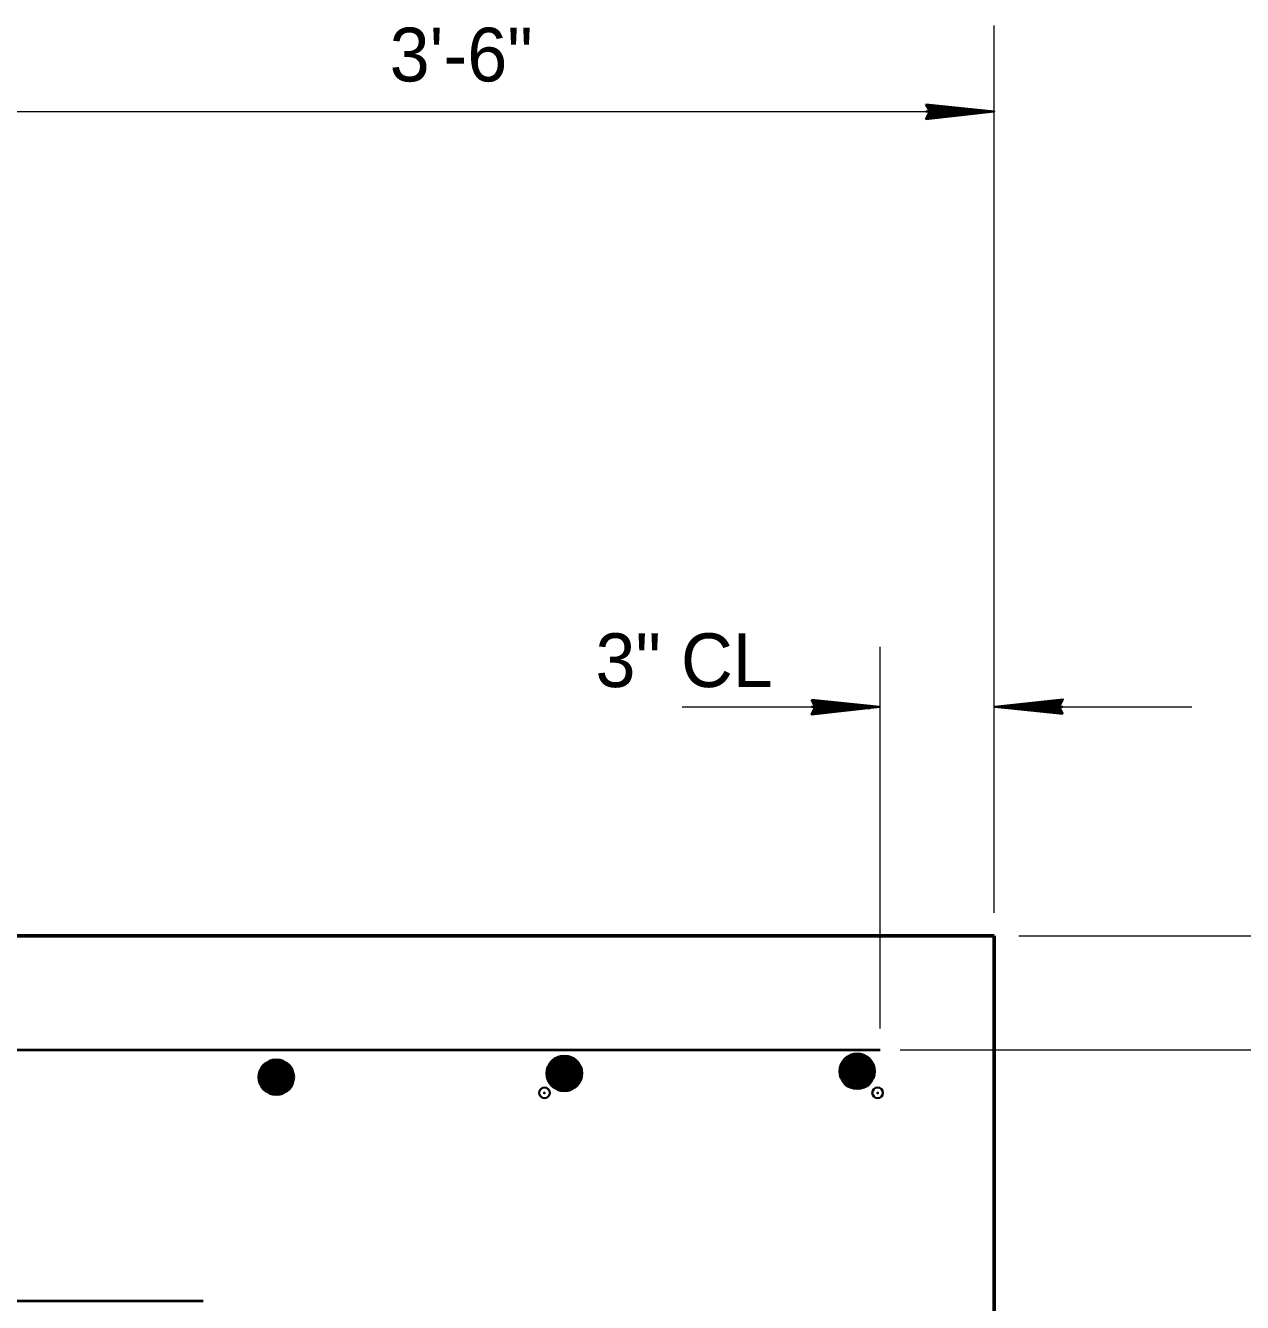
# Model space of a CAD drawing. Extents: x 4.49 to 7.69, y 0.28 to 2.27.
# Drawn here: x 6.6993 to 6.888, y 1.8987 to 2.0968 of the extents above; entities that cross this region are included whole.
import ezdxf

# ---------------------------------------------------------------- set-up
doc = ezdxf.new("R2010")
doc.units = 0
doc.header["$LTSCALE"] = 0.0033
doc.header["$PDMODE"] = 32
doc.header["$PDSIZE"] = 0.00165
doc.layers.add('1', color=7, linetype='Continuous', lineweight=35)

msp = doc.modelspace()

# ---------------------------------------------------------------- linework, layer by layer
at = {"layer": '1', "lineweight": 13}
for p, q in [((6.8495, 1.959167), (6.8495, 2.09675)), ((6.35025, 2.083417), (6.848917, 2.083417)), ((6.831833, 1.94125), (6.831833, 2.000417)), ((6.801083, 1.991083), (6.821917, 1.991083)), ((6.859333, 1.991083), (6.880167, 1.991083)), ((6.853333, 1.955583), (6.932833, 1.955583)), ((6.834917, 1.937917), (6.90475, 1.937917))]:
    msp.add_line(p, q, dxfattribs=at)
at = {"layer": '1'}
for p, q in [((6.838917, 2.083417), (6.8495, 2.083417)), ((6.839083, 2.08275), (6.846417, 2.0835)), ((6.839167, 2.084417), (6.847, 2.0835)), ((6.839167, 2.084417), (6.847, 2.0835)), ((6.839167, 2.084333), (6.847, 2.0835)), ((6.839167, 2.08425), (6.847, 2.083417)), ((6.839167, 2.08425), (6.847, 2.08325)), ((6.839167, 2.082583), (6.8465, 2.083417)), ((6.839167, 2.0825), (6.8465, 2.08325)), ((6.839167, 2.082333), (6.8465, 2.083167)), ((6.821417, 1.992083), (6.82925, 1.991167)), ((6.821417, 1.992083), (6.82925, 1.991167)), ((6.821417, 1.992), (6.82925, 1.991167)), ((6.859917, 1.992167), (6.852583, 1.991333)), ((6.859917, 1.992), (6.852583, 1.99125)), ((6.821167, 1.991083), (6.83175, 1.991083)), ((6.821333, 1.990417), (6.828667, 1.991167)), ((6.821417, 1.991917), (6.82925, 1.991083)), ((6.821417, 1.991917), (6.82925, 1.990917)), ((6.821417, 1.99025), (6.82875, 1.991083)), ((6.821417, 1.990167), (6.82875, 1.990917)), ((6.821417, 1.99), (6.82875, 1.990833)), ((6.860167, 1.991083), (6.849583, 1.991083)), ((6.859917, 1.99025), (6.852083, 1.99125)), ((6.859917, 1.99025), (6.852083, 1.991083)), ((6.859917, 1.990083), (6.852083, 1.991)), ((6.859917, 1.990083), (6.852083, 1.991)), ((6.859917, 1.990167), (6.852083, 1.991)), ((6.859917, 1.991917), (6.852583, 1.991083)), ((6.86, 1.99175), (6.852667, 1.991))]:
    msp.add_line(p, q, dxfattribs=at)
at = {"layer": '1', "lineweight": 40}
for p, q in [((6.367167, 1.937917), (6.831833, 1.937917)), ((6.785167, 1.9355), (6.783917, 1.936667)), ((6.826583, 1.9365), (6.830417, 1.935833)), ((6.8285, 1.935667), (6.829833, 1.936667)), ((6.830583, 1.935833), (6.829333, 1.937)), ((6.736083, 1.93525), (6.740667, 1.933083)), ((6.736333, 1.934833), (6.74025, 1.934083)), ((6.736333, 1.934667), (6.74025, 1.933917)), ((6.736417, 1.93525), (6.740333, 1.934583)), ((6.736417, 1.935083), (6.740333, 1.934333)), ((6.7365, 1.935583), (6.740333, 1.934917)), ((6.738417, 1.93475), (6.73975, 1.93575)), ((6.7405, 1.934917), (6.73925, 1.936083)), ((6.78075, 1.935833), (6.785333, 1.933667)), ((6.780917, 1.934833), (6.78475, 1.934167)), ((6.780917, 1.934667), (6.78475, 1.933917)), ((6.781, 1.935417), (6.784917, 1.934667)), ((6.781, 1.93525), (6.784917, 1.9345)), ((6.781, 1.935), (6.784833, 1.93425)), ((6.781083, 1.935833), (6.785, 1.935167)), ((6.781083, 1.935667), (6.785, 1.934917)), ((6.781167, 1.936167), (6.785, 1.9355)), ((6.783083, 1.935333), (6.784417, 1.936333)), ((6.826167, 1.936167), (6.83075, 1.934)), ((6.82625, 1.93475), (6.830083, 1.934)), ((6.82625, 1.934583), (6.830083, 1.933833)), ((6.826333, 1.935167), (6.830167, 1.9345)), ((6.826333, 1.935), (6.830167, 1.93425)), ((6.826417, 1.93575), (6.830333, 1.935)), ((6.826417, 1.935583), (6.830333, 1.934833)), ((6.826417, 1.935333), (6.83025, 1.934583)), ((6.8265, 1.936167), (6.830417, 1.9355)), ((6.8265, 1.936), (6.830417, 1.93525)), ((6.736, 1.933), (6.739917, 1.93225)), ((6.736, 1.932833), (6.739833, 1.932083)), ((6.736, 1.932583), (6.739833, 1.931917)), ((6.736083, 1.933417), (6.74, 1.932667)), ((6.736167, 1.933833), (6.74, 1.933083)), ((6.736167, 1.933667), (6.74, 1.932917)), ((6.73625, 1.93425), (6.740083, 1.933583)), ((6.73625, 1.934083), (6.740083, 1.933333)), ((6.736333, 1.934417), (6.740167, 1.933667)), ((6.780583, 1.933083), (6.784417, 1.932333)), ((6.780583, 1.932917), (6.784417, 1.932167)), ((6.780667, 1.933583), (6.784583, 1.932833)), ((6.780667, 1.933417), (6.7845, 1.932667)), ((6.780667, 1.933167), (6.7845, 1.9325)), ((6.78075, 1.934), (6.784667, 1.93325)), ((6.780833, 1.934417), (6.784667, 1.933667)), ((6.780833, 1.93425), (6.784667, 1.9335)), ((6.784917, 1.932667), (6.781167, 1.93225)), ((6.826, 1.933417), (6.829833, 1.932667)), ((6.826, 1.93325), (6.829833, 1.9325)), ((6.826083, 1.933917), (6.83, 1.933167)), ((6.826083, 1.93375), (6.829917, 1.933)), ((6.826083, 1.9335), (6.829917, 1.932833)), ((6.826167, 1.934333), (6.830083, 1.933583)), ((6.830333, 1.933), (6.826583, 1.932583)), ((6.735917, 1.9325), (6.73975, 1.93175)), ((6.735917, 1.932333), (6.73975, 1.931583)), ((6.74025, 1.932083), (6.7365, 1.931667))]:
    msp.add_line(p, q, dxfattribs=at)
at = {"layer": '1', "lineweight": 60}
for p, q in [((6.736333, 1.93525), (6.736167, 1.932333)), ((6.736583, 1.93525), (6.736333, 1.932333)), ((6.73675, 1.93525), (6.736583, 1.93225)), ((6.736917, 1.93525), (6.736667, 1.93225)), ((6.737083, 1.93525), (6.736917, 1.93225)), ((6.737333, 1.93525), (6.737167, 1.93225)), ((6.737583, 1.93525), (6.737333, 1.93225)), ((6.737667, 1.935167), (6.7375, 1.93225)), ((6.737833, 1.935167), (6.737667, 1.93225)), ((6.738, 1.935167), (6.737833, 1.93225)), ((6.73825, 1.935167), (6.738, 1.93225)), ((6.738417, 1.935167), (6.73825, 1.93225)), ((6.738667, 1.935083), (6.738417, 1.932167)), ((6.738917, 1.935083), (6.738667, 1.932167)), ((6.739083, 1.935083), (6.738917, 1.932167)), ((6.739167, 1.935083), (6.739, 1.932167)), ((6.739333, 1.935083), (6.739167, 1.932167)), ((6.739417, 1.935083), (6.73925, 1.932167)), ((6.739667, 1.935), (6.739417, 1.932083)), ((6.739833, 1.935), (6.739667, 1.932083)), ((6.74, 1.935), (6.73975, 1.932083)), ((6.740167, 1.935), (6.74, 1.932083)), ((6.740417, 1.935), (6.74025, 1.932083)), ((6.740667, 1.933083), (6.7405, 1.934917)), ((6.781, 1.935833), (6.780833, 1.932917)), ((6.78125, 1.935833), (6.781, 1.932917)), ((6.781417, 1.935833), (6.78125, 1.932833)), ((6.781583, 1.935833), (6.781333, 1.932833)), ((6.78175, 1.935833), (6.781583, 1.932833)), ((6.782, 1.935833), (6.781833, 1.932833)), ((6.78225, 1.935833), (6.782, 1.932833)), ((6.782333, 1.93575), (6.782167, 1.932833)), ((6.7825, 1.93575), (6.782333, 1.932833)), ((6.782667, 1.93575), (6.7825, 1.932833)), ((6.782917, 1.93575), (6.782667, 1.932833)), ((6.783083, 1.93575), (6.782917, 1.932833)), ((6.783333, 1.935667), (6.783083, 1.93275)), ((6.783583, 1.935667), (6.783333, 1.93275)), ((6.78375, 1.935667), (6.783583, 1.93275)), ((6.783833, 1.935667), (6.783667, 1.93275)), ((6.784, 1.935667), (6.783833, 1.93275)), ((6.784083, 1.935667), (6.783917, 1.93275)), ((6.784333, 1.935583), (6.784083, 1.932667)), ((6.7845, 1.935583), (6.784333, 1.932667)), ((6.784667, 1.935583), (6.784417, 1.932667)), ((6.784833, 1.935583), (6.784667, 1.932667)), ((6.785083, 1.935583), (6.784917, 1.932667)), ((6.785333, 1.933667), (6.785167, 1.9355)), ((6.826417, 1.936167), (6.82625, 1.93325)), ((6.826667, 1.936167), (6.826417, 1.93325)), ((6.826833, 1.936167), (6.826667, 1.933167)), ((6.827, 1.936167), (6.82675, 1.933167)), ((6.827167, 1.936167), (6.827, 1.933167)), ((6.827417, 1.936167), (6.82725, 1.933167)), ((6.827667, 1.936167), (6.827417, 1.933167)), ((6.82775, 1.936083), (6.827583, 1.933167)), ((6.827917, 1.936083), (6.82775, 1.933167)), ((6.828083, 1.936083), (6.827917, 1.933167)), ((6.828333, 1.936083), (6.828083, 1.933167)), ((6.8285, 1.936083), (6.828333, 1.933167)), ((6.82875, 1.936), (6.8285, 1.933083)), ((6.829, 1.936), (6.82875, 1.933083)), ((6.829167, 1.936), (6.829, 1.933083)), ((6.82925, 1.936), (6.829083, 1.933083)), ((6.829417, 1.936), (6.82925, 1.933083)), ((6.8295, 1.936), (6.829333, 1.933083)), ((6.82975, 1.935917), (6.8295, 1.933)), ((6.829917, 1.935917), (6.82975, 1.933)), ((6.830083, 1.935917), (6.829833, 1.933)), ((6.83025, 1.935917), (6.830083, 1.933)), ((6.8305, 1.935917), (6.830333, 1.933)), ((6.83075, 1.934), (6.830583, 1.935833)), ((6.740667, 1.933083), (6.735917, 1.932333)), ((6.785333, 1.933667), (6.780583, 1.932917)), ((6.83075, 1.934), (6.826, 1.93325))]:
    msp.add_line(p, q, dxfattribs=at)
at = {"layer": '1'}
for points in [[(6.838917, 2.0845), (6.8495, 2.083417), (6.838917, 2.08225), (6.8395, 2.083417)], [(6.839667, 2.0835), (6.844333, 2.083583), (6.844333, 2.0835), (6.843417, 2.0835), (6.839667, 2.083583), (6.842667, 2.083667), (6.8395, 2.08375), (6.84175, 2.083833), (6.8395, 2.083917), (6.843, 2.083667), (6.847667, 2.0835), (6.84675, 2.08325), (6.848, 2.08325), (6.839667, 2.08325), (6.842083, 2.083083), (6.8395, 2.083083), (6.844833, 2.0835), (6.8395, 2.082833)], [(6.821167, 1.992167), (6.83175, 1.991083), (6.821167, 1.989917), (6.82175, 1.991083)], [(6.860167, 1.99), (6.849583, 1.991083), (6.860167, 1.99225), (6.859583, 1.991083)], [(6.821917, 1.991167), (6.826583, 1.99125), (6.826583, 1.991167), (6.825667, 1.991167), (6.821917, 1.99125), (6.824917, 1.991333), (6.82175, 1.991417), (6.824, 1.9915), (6.82175, 1.991583), (6.82525, 1.991333), (6.829917, 1.991167), (6.829, 1.990917), (6.83025, 1.990917), (6.821917, 1.990917), (6.824333, 1.99075), (6.82175, 1.99075), (6.827083, 1.991167), (6.82175, 1.9905)], [(6.859417, 1.991), (6.85475, 1.990917), (6.85475, 1.991), (6.855667, 1.991), (6.859417, 1.990917), (6.856417, 1.990833), (6.859583, 1.99075), (6.857333, 1.990667), (6.859583, 1.990583), (6.856083, 1.990833), (6.851417, 1.991), (6.852333, 1.99125), (6.851083, 1.99125), (6.859417, 1.99125), (6.857, 1.991417), (6.859583, 1.991417), (6.85425, 1.991), (6.859583, 1.991667)]]:
    msp.add_lwpolyline(points, close=True, dxfattribs=at)
for points in [[(6.839667, 2.0835), (6.83925, 2.08425), (6.8395, 2.084), (6.839667, 2.083667), (6.839917, 2.08375), (6.83975, 2.084083), (6.839583, 2.083333), (6.839417, 2.082833), (6.839167, 2.082417)], [(6.859417, 1.991), (6.859833, 1.99025), (6.859583, 1.9905), (6.859417, 1.990833), (6.859167, 1.99075), (6.859333, 1.990417), (6.8595, 1.991167), (6.859667, 1.991667), (6.859917, 1.992083)], [(6.821917, 1.991167), (6.8215, 1.991917), (6.82175, 1.991667), (6.821917, 1.991333), (6.822167, 1.991417), (6.822, 1.99175), (6.821833, 1.991), (6.821667, 1.9905), (6.821417, 1.990083)]]:
    msp.add_lwpolyline(points, dxfattribs=at)
at = {"layer": '1', "lineweight": 60}
for points in [[(6.682833, 2.05975), (6.682833, 1.955583), (6.8495, 1.955583)], [(6.3495, 1.87225), (6.8495, 1.87225), (6.8495, 1.955583)], [(6.784417, 1.932167), (6.784417, 1.936333), (6.78275, 1.931667), (6.78325, 1.936833), (6.781167, 1.93225), (6.781917, 1.93675), (6.7835, 1.93175), (6.780333, 1.935083), (6.785167, 1.9355), (6.781917, 1.931833), (6.783917, 1.936667), (6.78075, 1.935833), (6.780583, 1.932917)], [(6.781167, 1.93225), (6.782667, 1.9345), (6.7805, 1.935417), (6.7825, 1.936833), (6.782667, 1.934583), (6.784333, 1.93225), (6.780333, 1.934583), (6.783083, 1.935333)], [(6.783917, 1.936667), (6.782667, 1.9345), (6.784917, 1.932667)], [(6.829833, 1.9325), (6.829833, 1.936667), (6.828167, 1.932), (6.828667, 1.937167), (6.826583, 1.932583), (6.827333, 1.937083), (6.828917, 1.932083), (6.82575, 1.935417), (6.830583, 1.935833), (6.827333, 1.932167), (6.829333, 1.937), (6.826167, 1.936167), (6.826, 1.93325)], [(6.826583, 1.932583), (6.828083, 1.934833), (6.825917, 1.93575), (6.827917, 1.937167), (6.828083, 1.934917), (6.82975, 1.932583), (6.82575, 1.934917), (6.8285, 1.935667)], [(6.829333, 1.937), (6.828083, 1.934833), (6.830333, 1.933)], [(6.7355, 1.933583), (6.740667, 1.93425), (6.736083, 1.93525)], [(6.73975, 1.931583), (6.73975, 1.93575), (6.738083, 1.931083), (6.738583, 1.93625), (6.7365, 1.931667), (6.73725, 1.936167), (6.738833, 1.931167), (6.735667, 1.9345), (6.7405, 1.934917), (6.73725, 1.93125), (6.73925, 1.936083), (6.736083, 1.93525), (6.735917, 1.932333)], [(6.7365, 1.931667), (6.738, 1.933917), (6.735833, 1.934833), (6.737833, 1.93625), (6.738, 1.934), (6.739667, 1.931667), (6.735667, 1.934), (6.738417, 1.93475)], [(6.73925, 1.936083), (6.738, 1.933917), (6.74025, 1.932083)], [(6.780167, 1.934167), (6.785333, 1.934833), (6.78075, 1.935833)], [(6.825583, 1.9345), (6.83075, 1.935167), (6.826167, 1.936167)]]:
    msp.add_lwpolyline(points, dxfattribs=at)
at = {"layer": '1', "lineweight": 40}
for points in [[(6.664333, 2.012), (6.664333, 1.899), (6.726833, 1.899)], [(6.735917, 1.932333), (6.738, 1.931083), (6.73975, 1.931583), (6.740667, 1.933083)], [(6.780583, 1.932917), (6.782667, 1.931667), (6.784417, 1.932167), (6.785333, 1.933667)], [(6.826, 1.93325), (6.828083, 1.932), (6.829833, 1.9325), (6.83075, 1.934)]]:
    msp.add_lwpolyline(points, dxfattribs=at)
at = {"layer": '1', "lineweight": 60}
for centre in [(6.782833, 1.934267), (6.82825, 1.9346), (6.738167, 1.933683)]:
    msp.add_circle(centre, 0.00264, dxfattribs=at)
at = {"layer": '1'}
for p in [(6.73725, 1.932917), (6.783167, 1.932917), (6.829083, 1.932917), (6.77975, 1.93125), (6.831417, 1.93125)]:
    msp.add_point(p, dxfattribs=at)

# ---------------------------------------------------------------- texts
for s, height, p in [('3\'-6"', 0.008333, (6.75575, 2.088083)), ('3" CL', 0.008334, (6.787667, 1.994167))]:
    msp.add_text(s, height=height, dxfattribs=at).set_placement(p)

doc.saveas('drawing.dxf')
